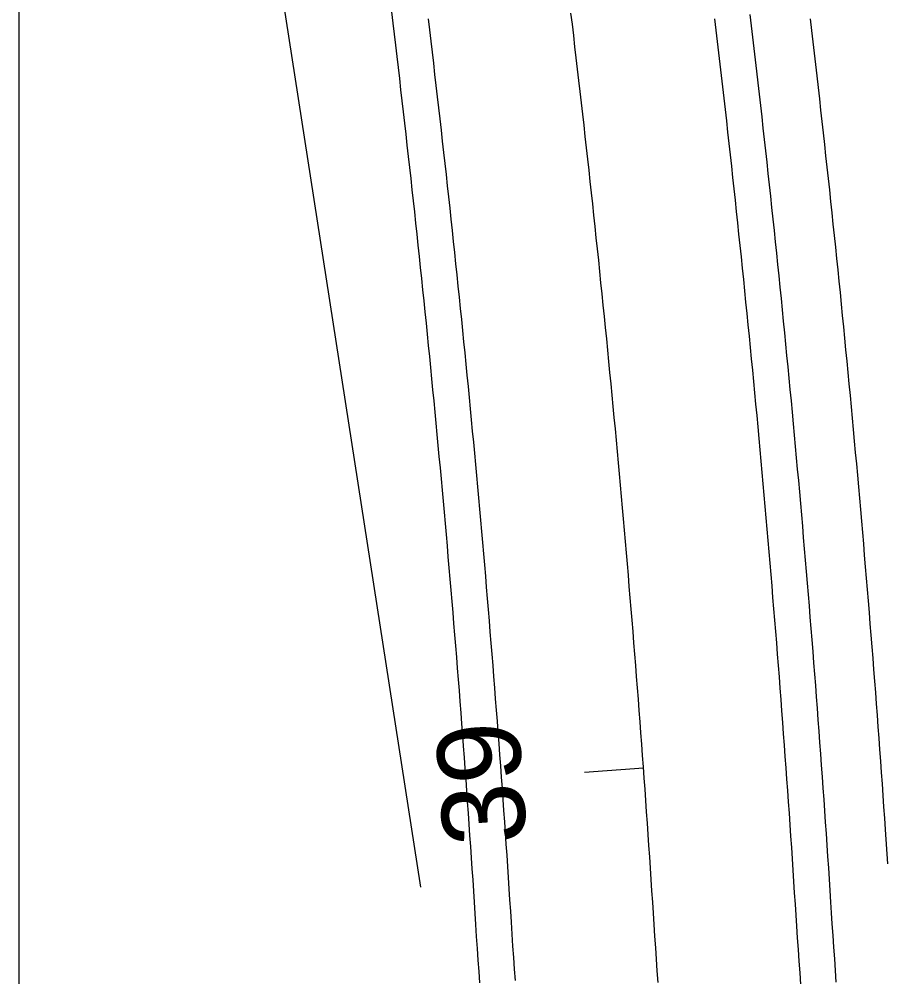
# Model space of a CAD drawing. Extents: x 2318076 to 2324211, y 613525 to 630327.
# Drawn here: x 2318880.5 to 2318953.7, y 618817.3 to 618898.1 of the extents above; entities that cross this region are included whole.
import ezdxf

# ---------------------------------------------------------------- set-up
doc = ezdxf.new("R2010")
doc.units = 0
for name, color, linetype in [('GE_P_CL_50', 7, 'Continuous'), ('PV_P_EOP', 7, 'Continuous'), ('PV_P_Shoulder', 7, 'Continuous'), ('RD_X_GR_Lt', 7, 'Continuous'), ('RD_X_GR_Rt', 7, 'Continuous'), ('SC_Scratch3', 7, 'Continuous')]:
    doc.layers.add(name, color=color, linetype=linetype)

msp = doc.modelspace()

# ---------------------------------------------------------------- linework, layer by layer
at = {"layer": 'GE_P_CL_50'}
msp.add_line((2318933.119, 618834.878), (2318928.132, 618834.517), dxfattribs=at)
msp.add_lwpolyline([(2318934.347, 618816.827), (2318934.281, 618817.802), (2318934.214, 618818.776), (2318934.147, 618819.751), (2318934.079, 618820.726), (2318934.01, 618821.7), (2318933.95, 618822.651), (2318933.889, 618823.602), (2318933.828, 618824.552), (2318933.766, 618825.503), (2318933.703, 618826.454), (2318933.64, 618827.404), (2318933.576, 618828.355), (2318933.511, 618829.305), (2318933.446, 618830.256), (2318933.38, 618831.207), (2318933.313, 618832.157), (2318933.246, 618833.107), (2318933.178, 618834.058), (2318933.109, 618835.008), (2318933.04, 618835.959), (2318932.97, 618836.909), (2318932.899, 618837.859), (2318932.828, 618838.809), (2318932.756, 618839.76), (2318932.683, 618840.71), (2318932.61, 618841.66), (2318932.536, 618842.61), (2318932.461, 618843.56), (2318932.386, 618844.51), (2318932.31, 618845.46), (2318932.233, 618846.41), (2318932.156, 618847.36), (2318932.078, 618848.31), (2318932, 618849.259), (2318931.92, 618850.209), (2318931.84, 618851.159), (2318931.76, 618852.109), (2318931.679, 618853.058), (2318931.597, 618854.008), (2318931.514, 618854.957), (2318931.431, 618855.907), (2318931.347, 618856.856), (2318931.262, 618857.805), (2318931.177, 618858.755), (2318931.091, 618859.704), (2318931.005, 618860.653), (2318930.917, 618861.602), (2318930.83, 618862.552), (2318930.741, 618863.501), (2318930.652, 618864.45), (2318930.562, 618865.399), (2318930.471, 618866.348), (2318930.38, 618867.296), (2318930.288, 618868.245), (2318930.196, 618869.194), (2318930.103, 618870.143), (2318930.009, 618871.091), (2318929.914, 618872.04), (2318929.819, 618872.988), (2318929.723, 618873.937), (2318929.627, 618874.885), (2318929.53, 618875.833), (2318929.432, 618876.782), (2318929.334, 618877.73), (2318929.234, 618878.678), (2318929.135, 618879.626), (2318929.034, 618880.574), (2318928.933, 618881.522), (2318928.831, 618882.47), (2318928.729, 618883.418), (2318928.626, 618884.366), (2318928.522, 618885.313), (2318928.418, 618886.261), (2318928.313, 618887.209), (2318928.207, 618888.156), (2318928.1, 618889.104), (2318927.993, 618890.051), (2318927.886, 618890.998), (2318927.777, 618891.945), (2318927.668, 618892.893), (2318927.559, 618893.84), (2318927.448, 618894.787), (2318927.337, 618895.734), (2318927.226, 618896.68), (2318927.113, 618897.627), (2318927, 618898.574)], dxfattribs=at)
at = {"layer": 'PV_P_EOP'}
for points in [[(2318922.308, 618816.986), (2318922.242, 618817.953), (2318922.175, 618818.92), (2318922.108, 618819.887), (2318922.037, 618820.901), (2318921.974, 618821.89), (2318921.914, 618822.833), (2318921.853, 618823.775), (2318921.792, 618824.718), (2318921.729, 618825.66), (2318921.667, 618826.602), (2318921.603, 618827.544), (2318921.539, 618828.487), (2318921.474, 618829.429), (2318921.409, 618830.371), (2318921.343, 618831.313), (2318921.276, 618832.255), (2318921.209, 618833.197), (2318921.141, 618834.139), (2318921.072, 618835.081), (2318921.003, 618836.023), (2318920.933, 618836.965), (2318920.862, 618837.907), (2318920.79, 618838.849), (2318920.718, 618839.791), (2318920.646, 618840.733), (2318920.573, 618841.674), (2318920.499, 618842.616), (2318920.424, 618843.558), (2318920.349, 618844.499), (2318920.273, 618845.441), (2318920.196, 618846.383), (2318920.119, 618847.324), (2318920.041, 618848.265), (2318919.962, 618849.207), (2318919.883, 618850.148), (2318919.803, 618851.09), (2318919.723, 618852.031), (2318919.641, 618852.972), (2318919.56, 618853.913), (2318919.477, 618854.854), (2318919.394, 618855.796), (2318919.31, 618856.737), (2318919.226, 618857.678), (2318919.14, 618858.619), (2318919.055, 618859.559), (2318918.968, 618860.5), (2318918.881, 618861.441), (2318918.793, 618862.382), (2318918.705, 618863.322), (2318918.616, 618864.263), (2318918.526, 618865.204), (2318918.436, 618866.144), (2318918.345, 618867.085), (2318918.253, 618868.025), (2318918.161, 618868.966), (2318918.068, 618869.906), (2318917.974, 618870.846), (2318917.88, 618871.786), (2318917.785, 618872.726), (2318917.689, 618873.667), (2318917.593, 618874.607), (2318917.496, 618875.546), (2318917.398, 618876.486), (2318917.3, 618877.426), (2318917.201, 618878.366), (2318917.101, 618879.306), (2318917.001, 618880.245), (2318916.9, 618881.185), (2318916.799, 618882.124), (2318916.697, 618883.064), (2318916.594, 618884.003), (2318916.49, 618884.943), (2318916.386, 618885.882), (2318916.281, 618886.821), (2318916.176, 618887.76), (2318916.07, 618888.699), (2318915.963, 618889.638), (2318915.856, 618890.577), (2318915.748, 618891.516), (2318915.639, 618892.455), (2318915.529, 618893.394), (2318915.419, 618894.332), (2318915.309, 618895.271), (2318915.197, 618896.209), (2318915.085, 618897.148), (2318914.973, 618898.086)], [(2318946.386, 618816.653), (2318946.32, 618817.635), (2318946.253, 618818.618), (2318946.186, 618819.6), (2318946.118, 618820.582), (2318946.049, 618821.564), (2318945.983, 618822.5), (2318945.926, 618823.411), (2318945.865, 618824.37), (2318945.803, 618825.329), (2318945.74, 618826.288), (2318945.677, 618827.247), (2318945.613, 618828.206), (2318945.548, 618829.165), (2318945.483, 618830.124), (2318945.417, 618831.083), (2318945.351, 618832.042), (2318945.283, 618833.001), (2318945.216, 618833.96), (2318945.147, 618834.918), (2318945.078, 618835.877), (2318945.008, 618836.836), (2318944.937, 618837.794), (2318944.866, 618838.753), (2318944.794, 618839.712), (2318944.721, 618840.67), (2318944.648, 618841.629), (2318944.574, 618842.587), (2318944.499, 618843.546), (2318944.424, 618844.504), (2318944.348, 618845.462), (2318944.272, 618846.421), (2318944.194, 618847.379), (2318944.116, 618848.337), (2318944.038, 618849.295), (2318943.958, 618850.253), (2318943.878, 618851.211), (2318943.798, 618852.169), (2318943.717, 618853.127), (2318943.635, 618854.085), (2318943.552, 618855.043), (2318943.469, 618856.001), (2318943.385, 618856.959), (2318943.3, 618857.917), (2318943.215, 618858.874), (2318943.129, 618859.832), (2318943.042, 618860.79), (2318942.955, 618861.747), (2318942.867, 618862.705), (2318942.778, 618863.662), (2318942.689, 618864.619), (2318942.599, 618865.577), (2318942.508, 618866.534), (2318942.417, 618867.491), (2318942.325, 618868.448), (2318942.232, 618869.406), (2318942.139, 618870.363), (2318942.045, 618871.32), (2318941.95, 618872.277), (2318941.855, 618873.233), (2318941.759, 618874.19), (2318941.662, 618875.147), (2318941.565, 618876.104), (2318941.467, 618877.06), (2318941.368, 618878.017), (2318941.269, 618878.974), (2318941.169, 618879.93), (2318941.068, 618880.886), (2318940.967, 618881.843), (2318940.865, 618882.799), (2318940.762, 618883.755), (2318940.659, 618884.711), (2318940.555, 618885.667), (2318940.45, 618886.623), (2318940.345, 618887.579), (2318940.239, 618888.535), (2318940.132, 618889.491), (2318940.025, 618890.447), (2318939.917, 618891.402), (2318939.808, 618892.358), (2318939.699, 618893.314), (2318939.589, 618894.269), (2318939.478, 618895.224), (2318939.367, 618896.18), (2318939.255, 618897.135), (2318939.142, 618898.09)]]:
    msp.add_lwpolyline(points, dxfattribs=at)
at = {"layer": 'PV_P_Shoulder'}
for points in [[(2318919.315, 618816.782), (2318919.249, 618817.747), (2318919.183, 618818.712), (2318919.115, 618819.677), (2318919.043, 618820.701), (2318918.98, 618821.7), (2318918.92, 618822.641), (2318918.859, 618823.581), (2318918.798, 618824.521), (2318918.736, 618825.461), (2318918.673, 618826.402), (2318918.61, 618827.342), (2318918.546, 618828.282), (2318918.481, 618829.222), (2318918.416, 618830.162), (2318918.35, 618831.102), (2318918.284, 618832.042), (2318918.216, 618832.982), (2318918.149, 618833.922), (2318918.08, 618834.862), (2318918.011, 618835.802), (2318917.941, 618836.742), (2318917.87, 618837.682), (2318917.799, 618838.621), (2318917.727, 618839.561), (2318917.655, 618840.501), (2318917.582, 618841.441), (2318917.508, 618842.38), (2318917.433, 618843.32), (2318917.358, 618844.259), (2318917.282, 618845.199), (2318917.206, 618846.138), (2318917.129, 618847.078), (2318917.051, 618848.017), (2318916.973, 618848.956), (2318916.894, 618849.896), (2318916.814, 618850.835), (2318916.734, 618851.774), (2318916.653, 618852.713), (2318916.571, 618853.652), (2318916.489, 618854.591), (2318916.406, 618855.53), (2318916.322, 618856.469), (2318916.238, 618857.408), (2318916.153, 618858.347), (2318916.067, 618859.286), (2318915.981, 618860.225), (2318915.894, 618861.163), (2318915.806, 618862.102), (2318915.718, 618863.041), (2318915.629, 618863.979), (2318915.54, 618864.918), (2318915.45, 618865.856), (2318915.359, 618866.795), (2318915.267, 618867.733), (2318915.175, 618868.671), (2318915.082, 618869.609), (2318914.989, 618870.548), (2318914.895, 618871.486), (2318914.8, 618872.424), (2318914.705, 618873.362), (2318914.608, 618874.3), (2318914.512, 618875.238), (2318914.414, 618876.175), (2318914.316, 618877.113), (2318914.218, 618878.051), (2318914.118, 618878.989), (2318914.018, 618879.926), (2318913.918, 618880.864), (2318913.816, 618881.801), (2318913.714, 618882.738), (2318913.612, 618883.676), (2318913.508, 618884.613), (2318913.405, 618885.55), (2318913.3, 618886.487), (2318913.195, 618887.424), (2318913.089, 618888.361), (2318912.982, 618889.298), (2318912.875, 618890.235), (2318912.767, 618891.172), (2318912.659, 618892.109), (2318912.55, 618893.045), (2318912.44, 618893.982), (2318912.329, 618894.918), (2318912.218, 618895.855), (2318912.107, 618896.791), (2318911.994, 618897.727), (2318911.881, 618898.664)], [(2318949.379, 618816.853), (2318949.313, 618817.837), (2318949.246, 618818.822), (2318949.179, 618819.806), (2318949.111, 618820.79), (2318949.042, 618821.774), (2318948.977, 618822.699), (2318948.92, 618823.601), (2318948.858, 618824.562), (2318948.796, 618825.524), (2318948.734, 618826.485), (2318948.67, 618827.446), (2318948.606, 618828.407), (2318948.542, 618829.368), (2318948.476, 618830.329), (2318948.41, 618831.29), (2318948.343, 618832.251), (2318948.276, 618833.212), (2318948.208, 618834.173), (2318948.139, 618835.134), (2318948.07, 618836.094), (2318948, 618837.055), (2318947.929, 618838.016), (2318947.858, 618838.977), (2318947.785, 618839.937), (2318947.713, 618840.898), (2318947.639, 618841.858), (2318947.565, 618842.819), (2318947.49, 618843.779), (2318947.415, 618844.74), (2318947.339, 618845.7), (2318947.262, 618846.661), (2318947.185, 618847.621), (2318947.106, 618848.581), (2318947.028, 618849.542), (2318946.948, 618850.502), (2318946.868, 618851.462), (2318946.787, 618852.422), (2318946.706, 618853.382), (2318946.624, 618854.342), (2318946.541, 618855.302), (2318946.457, 618856.262), (2318946.373, 618857.222), (2318946.288, 618858.182), (2318946.203, 618859.142), (2318946.117, 618860.101), (2318946.03, 618861.061), (2318945.942, 618862.021), (2318945.854, 618862.98), (2318945.765, 618863.94), (2318945.676, 618864.899), (2318945.586, 618865.859), (2318945.495, 618866.818), (2318945.403, 618867.777), (2318945.311, 618868.737), (2318945.218, 618869.696), (2318945.125, 618870.655), (2318945.03, 618871.614), (2318944.936, 618872.573), (2318944.84, 618873.532), (2318944.744, 618874.491), (2318944.647, 618875.45), (2318944.549, 618876.408), (2318944.451, 618877.367), (2318944.352, 618878.326), (2318944.253, 618879.284), (2318944.153, 618880.243), (2318944.052, 618881.201), (2318943.95, 618882.16), (2318943.848, 618883.118), (2318943.745, 618884.076), (2318943.642, 618885.035), (2318943.537, 618885.993), (2318943.432, 618886.951), (2318943.327, 618887.909), (2318943.221, 618888.867), (2318943.114, 618889.825), (2318943.006, 618890.783), (2318942.898, 618891.74), (2318942.789, 618892.698), (2318942.68, 618893.656), (2318942.569, 618894.613), (2318942.458, 618895.571), (2318942.347, 618896.528), (2318942.235, 618897.485), (2318942.122, 618898.442)]]:
    msp.add_lwpolyline(points, dxfattribs=at)
at = {"layer": 'RD_X_GR_Lt'}
msp.add_line((2318914.324, 618824.85), (2318899.884, 618918.122), dxfattribs=at)
at = {"layer": 'RD_X_GR_Rt'}
msp.add_lwpolyline([(2318953.725, 618826.81), (2318953.53, 618829.706), (2318953.465, 618830.67), (2318953.398, 618831.635), (2318953.331, 618832.599), (2318953.264, 618833.563), (2318953.195, 618834.528), (2318953.126, 618835.492), (2318953.057, 618836.456), (2318952.986, 618837.421), (2318952.915, 618838.385), (2318952.844, 618839.349), (2318952.771, 618840.313), (2318952.698, 618841.277), (2318952.625, 618842.241), (2318952.55, 618843.205), (2318952.475, 618844.169), (2318952.399, 618845.133), (2318952.323, 618846.097), (2318952.246, 618847.061), (2318952.168, 618848.025), (2318952.09, 618848.989), (2318952.011, 618849.952), (2318951.931, 618850.916), (2318951.851, 618851.88), (2318951.769, 618852.843), (2318951.688, 618853.807), (2318951.605, 618854.77), (2318951.522, 618855.734), (2318951.438, 618856.697), (2318951.354, 618857.66), (2318951.269, 618858.624), (2318951.183, 618859.587), (2318951.096, 618860.55), (2318951.009, 618861.513), (2318950.921, 618862.476), (2318950.833, 618863.439), (2318950.744, 618864.402), (2318950.654, 618865.365), (2318950.563, 618866.328), (2318950.472, 618867.291), (2318950.38, 618868.254), (2318950.288, 618869.217), (2318950.195, 618870.179), (2318950.101, 618871.142), (2318950.006, 618872.104), (2318949.911, 618873.067), (2318949.815, 618874.029), (2318949.719, 618874.992), (2318949.621, 618875.954), (2318949.524, 618876.916), (2318949.425, 618877.878), (2318949.326, 618878.841), (2318949.226, 618879.803), (2318949.125, 618880.765), (2318949.024, 618881.727), (2318948.922, 618882.688), (2318948.82, 618883.65), (2318948.716, 618884.612), (2318948.612, 618885.574), (2318948.508, 618886.535), (2318948.403, 618887.497), (2318948.297, 618888.458), (2318948.19, 618889.42), (2318948.083, 618890.381), (2318947.975, 618891.342), (2318947.866, 618892.303), (2318947.757, 618893.265), (2318947.647, 618894.226), (2318947.536, 618895.187), (2318947.425, 618896.148), (2318947.313, 618897.108), (2318947.2, 618898.069)], dxfattribs=at)
at = {"layer": 'SC_Scratch3'}
msp.add_line((2318880.454, 614778.412), (2318880.454, 630327.224), dxfattribs=at)

# ---------------------------------------------------------------- texts
at = {"layer": 'GE_P_CL_50'}
msp.add_text('39', height=7, rotation=94.13216, dxfattribs=at).set_placement((2318923.288, 618828.648))

doc.saveas('drawing.dxf')
